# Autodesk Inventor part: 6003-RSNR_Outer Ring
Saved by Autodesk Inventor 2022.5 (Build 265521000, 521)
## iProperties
Created: 2024-12
Part Number: 6003-RSNR_Outer Ring
Material: Generic
Document SubType Name: Modeling
Designer: AdminForWorker
Density: 1 g/cm^3
Appearance: Default
Title: 6003-RSNR_Outer Ring
Author: AdminForWorker
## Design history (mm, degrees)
feature "Body1"
body "Solid1"
